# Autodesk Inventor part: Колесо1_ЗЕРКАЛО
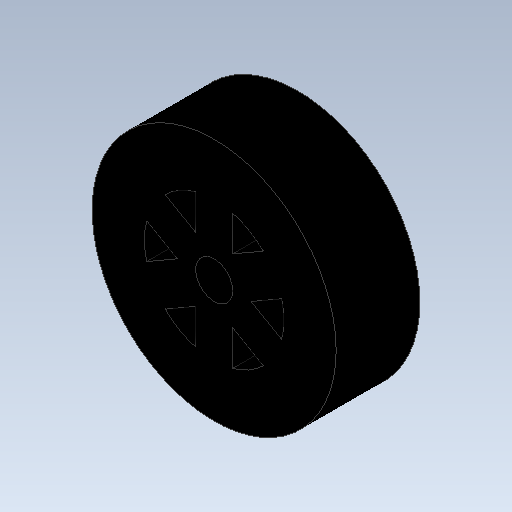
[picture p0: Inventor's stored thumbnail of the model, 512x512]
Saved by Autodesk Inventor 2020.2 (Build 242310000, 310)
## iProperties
Created: 2020-04
Part Number: Колесо1_ЗЕРКАЛО
Material: Типовые
Document SubType Name: Modeling
Designer: Алексей
Density: 1 g/cm^3
Appearance: По умолчанию
Author: Алексей
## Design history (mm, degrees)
derived "Колесо1.ipt"
  sketch "Эскиз1"
    geometry: L1 (-54.75, 13.28)-(7.25, 13.28) reference; L2 (-26.4, 15.912)-(-26.4, -3.373) reference; L3 (-26.4, -3.373)-(-21.1, -3.373) reference; L4 (-21.1, -3.373)-(-21.1, 15.912) reference; L5 (-14.074, 3.744)-(-30.776, 13.386) reference; L6 (-33.426, 8.796)-(-16.724, -0.846) reference; L7 (-16.724, 13.386)-(-33.426, 3.744) reference; L8 (-30.776, -0.846)-(-14.074, 8.796) reference; L9 (-26.4, 15.912)-(-26.4, -3.373) reference; L10 (-21.1, -3.373)-(-21.1, 15.912) reference; L11 (-33.426, 8.796)-(-16.724, -0.846) reference; L12 (-14.074, 3.744)-(-30.776, 13.386) reference; L13 (-30.776, -0.846)-(-14.074, 8.796) reference; L14 (-16.724, 13.386)-(-33.426, 3.744) reference; C1 r 17.5 at (-23.75, 6.27) reference; C2 r 10 at (-23.75, 6.27) reference; C3 r 10 at (-23.75, 6.27) reference; C4 r 10 at (-23.75, 6.27) reference; C5 r 10 at (-23.75, 6.27) reference; C6 r 10 at (-23.75, 6.27) reference; C7 r 2.65 at (-23.75, 6.27) reference; A1 r 10 centre (-23.75, 6.27) between (-30.776, 13.386) and (-33.426, 8.796) reference; 4 further points
    constraints: 1 other
  sketch "Эскиз2"
    geometry: C1 r 17.5 at (0, 0) reference; C2 r 10 at (0, 0) reference; 1 further point
  sketch "Эскиз3"
    geometry: C1 r 2.65 at (-23.75, 6.27) reference; C2 r 5 at (-23.75, 6.27) reference; 1 further point
feature "Твердое тело1::Колесо1.ipt"
tag "Элемент создания тегов1"
node "Твердое тело1"
